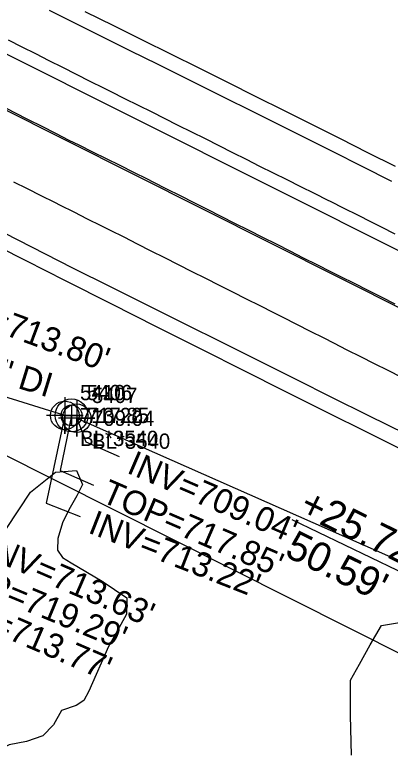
# Model space of a CAD drawing. Extents: x 1516784 to 1522736, y 634838 to 639369.
# Drawn here: x 1519791.7 to 1519853.3, y 638354.5 to 638475.3 of the extents above; entities that cross this region are included whole.
import ezdxf

# ---------------------------------------------------------------- set-up
doc = ezdxf.new("R2010")
doc.units = 0
for name, color, linetype in [('COGO Default Point Elevation', 7, 'Continuous'), ('COGO Default Point Number', 7, 'Continuous'), ('Exist Environmental Wetland Boundary Cogo Number', 7, 'Continuous'), ('Exist Environmental Wetland Boundary Text', 7, 'Continuous'), ('Exist Property Tie Line Leader', 7, 'Continuous'), ('Exist Property Tie Line Text', 7, 'Continuous'), ('Exist Right of Way Line', 7, 'Continuous'), ('Exist Utilities Sanitary Sewer Manhole CELL', 7, 'Continuous'), ('Exist Utilities Sanitary Sewer Manhole Cogo Elevation', 7, 'Continuous'), ('Exist Utilities Sanitary Sewer Manhole Cogo Number', 7, 'Continuous'), ('Exist Utilities Sanitary Sewer Manhole Leader', 7, 'Continuous'), ('Exist Utilities Sanitary Sewer Manhole Text', 7, 'Continuous'), ('Exist Utilities Sanitary Sewer UG Line', 7, 'Continuous'), ('Exist Utilities Sanitary Sewer UG Line Cogo Comment', 7, 'Continuous'), ('Exist Utilities Sanitary Sewer UG Line Cogo Elevation', 7, 'Continuous'), ('Exist Utilities Sanitary Sewer UG Line Cogo Number', 7, 'Continuous'), ('Exist Utilities Sanitary Sewer UG Line Cogo Point CELL', 7, 'Continuous'), ('Exist Utilities Sanitary Sewer UG Line Invert Elevation', 7, 'Continuous'), ('Exist Utilities Sanitary Sewer UG Line Leader', 7, 'Continuous'), ('Exist Utilities Sanitary Sewer UG Line Text', 7, 'Continuous'), ('Exist Utilities Water UG Line SUE LOS B', 7, 'Continuous'), ('Exist Vegetation Hedge Row', 7, 'Continuous')]:
    doc.layers.add(name, color=color, linetype=linetype)

msp = doc.modelspace()

# ---------------------------------------------------------------- linework, layer by layer
at = {"layer": 'COGO Default Point Elevation'}
for points in [[(1519790.67, 638471.18), (1519792.9, 638470.06), (1519795.13, 638468.93), (1519797.36, 638467.81), (1519799.59, 638466.68), (1519801.82, 638465.55), (1519804.05, 638464.43), (1519806.28, 638463.3), (1519807.48, 638462.7), (1519809.71, 638461.59), (1519811.95, 638460.48), (1519814.19, 638459.36), (1519816.25, 638458.34), (1519818.48, 638457.22), (1519820.71, 638456.11), (1519822.95, 638454.99), (1519825.18, 638453.87), (1519827.42, 638452.75), (1519829.65, 638451.63), (1519831.88, 638450.51), (1519834.12, 638449.39), (1519836.35, 638448.28), (1519838.59, 638447.16), (1519840.82, 638446.04), (1519843.06, 638444.92), (1519843.44, 638444.73), (1519845.68, 638443.61), (1519847.91, 638442.49), (1519850.15, 638441.37), (1519851.81, 638440.54), (1519854.04, 638439.42)], [(1519854.12, 638427.88), (1519851.88, 638429), (1519849.65, 638430.12), (1519847.41, 638431.24), (1519845.18, 638432.36), (1519843.56, 638433.17), (1519841.33, 638434.3), (1519839.1, 638435.42), (1519836.87, 638436.55), (1519834.64, 638437.68), (1519832.41, 638438.8), (1519830.17, 638439.93), (1519830.06, 638439.99), (1519827.83, 638441.11), (1519825.6, 638442.24), (1519823.36, 638443.36), (1519821.13, 638444.49), (1519818.9, 638445.61), (1519816.67, 638446.74), (1519814.44, 638447.87), (1519813.48, 638448.35), (1519811.24, 638449.46), (1519809, 638450.57), (1519806.76, 638451.68), (1519804.53, 638452.79), (1519802.29, 638453.91), (1519800.69, 638454.7), (1519798.46, 638455.83), (1519796.24, 638456.96), (1519794.01, 638458.09), (1519791.78, 638459.22), (1519789.56, 638460.35)], [(1519791.56, 638447.93), (1519793.8, 638446.81), (1519796.03, 638445.69), (1519798.26, 638444.57), (1519799.17, 638444.11), (1519801.41, 638442.99), (1519803.64, 638441.87), (1519805.88, 638440.75), (1519807.38, 638440), (1519809.61, 638438.88), (1519811.84, 638437.75), (1519814.07, 638436.63), (1519816.3, 638435.5), (1519818.54, 638434.38), (1519820.77, 638433.25), (1519823, 638432.13), (1519825.23, 638431), (1519827.46, 638429.88), (1519829.69, 638428.75), (1519831.92, 638427.63), (1519834.15, 638426.51), (1519835.71, 638425.72), (1519837.94, 638424.59), (1519840.17, 638423.46), (1519842.4, 638422.34), (1519843.97, 638421.54), (1519846.2, 638420.42), (1519848.43, 638419.3), (1519850.66, 638418.17), (1519852.9, 638417.05), (1519855.13, 638415.93)]]:
    msp.add_lwpolyline(points, dxfattribs=at)
at = {"layer": 'COGO Default Point Number'}
for points in [[(1519855.99, 638406.51), (1519849.67, 638409.64), (1519843.73, 638412.59), (1519837.89, 638415.51), (1519832.06, 638418.43), (1519825.95, 638421.5), (1519819.59, 638424.68), (1519813.47, 638427.73), (1519807.57, 638430.65), (1519801.28, 638433.8), (1519794.56, 638437.2), (1519787.76, 638440.67), (1519780.89, 638444.19), (1519773.8, 638447.8), (1519766.5, 638451.49), (1519759.18, 638455.17), (1519751.88, 638458.82), (1519744.56, 638462.49), (1519737.21, 638466.19), (1519729.84, 638469.9), (1519722.47, 638473.61), (1519715.13, 638477.28)], [(1519797.37, 638476.04), (1519806.15, 638471.68), (1519810.62, 638469.46), (1519815.21, 638467.18), (1519819.9, 638464.85), (1519824.69, 638462.47), (1519831.97, 638458.85), (1519836.76, 638456.45), (1519843.88, 638452.88), (1519848.65, 638450.48), (1519853.49, 638448.05)]]:
    msp.add_lwpolyline(points, dxfattribs=at)
at = {"layer": 'Exist Environmental Wetland Boundary Cogo Number'}
for points in [[(1519803.26, 638475.84), (1519807.96, 638473.51), (1519812.62, 638471.19), (1519817.28, 638468.88), (1519821.94, 638466.57), (1519826.6, 638464.25), (1519831.27, 638461.92), (1519835.91, 638459.6), (1519840.51, 638457.3), (1519845.07, 638455.01), (1519849.58, 638452.74), (1519854.09, 638450.47)], [(1519782.28, 638438.89), (1519782.81, 638439.16), (1519783.21, 638439.34), (1519783.53, 638439.46), (1519783.88, 638439.53), (1519784.05, 638439.55), (1519784.21, 638439.55), (1519784.37, 638439.54), (1519784.51, 638439.5), (1519784.82, 638439.4), (1519785.21, 638439.22), (1519786.39, 638438.64), (1519789.09, 638437.29), (1519793.55, 638435.04), (1519800, 638431.77), (1519807.48, 638427.99), (1519815.01, 638424.18), (1519822.36, 638420.49), (1519829.29, 638417.01), (1519835.92, 638413.69), (1519842.37, 638410.47), (1519850.04, 638406.65), (1519854.86, 638404.25)]]:
    msp.add_lwpolyline(points, dxfattribs=at)
at = {"layer": 'Exist Environmental Wetland Boundary Text'}
msp.add_line((1519517.96, 638596.36), (1520558.73, 638073.97), dxfattribs=at)
at = {"layer": 'Exist Property Tie Line Leader'}
msp.add_lwpolyline([(1519886.4, 638381.42), (1519858.81, 638382.15), (1519837.21, 638392.55)], dxfattribs=at)
at = {"layer": 'Exist Right of Way Line'}
msp.add_line((1519230.66, 638683.96), (1520000.91, 638297.35), dxfattribs=at)
at = {"layer": 'Exist Utilities Sanitary Sewer Manhole CELL'}
msp.add_lwpolyline([(1519801.06, 638411.36), (1519801.06, 638407.94), (1519801.06, 638409.65), (1519802.77, 638409.65), (1519799.35, 638409.65)], dxfattribs=at)
for radius in [2.69, 1.71]:
    msp.add_circle((1519801.06, 638409.65), radius, dxfattribs=at)
at = {"layer": 'Exist Utilities Sanitary Sewer Manhole Leader'}
msp.add_lwpolyline([(1519801.06, 638409.65), (1519799.17, 638400.61), (1519804.68, 638398.23)], dxfattribs=at)
at = {"layer": 'Exist Utilities Sanitary Sewer UG Line'}
for p, q in [((1519799.95, 638409.64), (1519774.57, 638417.48)), ((1519801.9, 638409.18), (1519994.43, 638324.11))]:
    msp.add_line(p, q, dxfattribs=at)
at = {"layer": 'Exist Utilities Sanitary Sewer UG Line Cogo Point CELL'}
for points in [[(1519799.95, 638412.64), (1519799.95, 638406.64), (1519799.95, 638409.64), (1519802.95, 638409.64), (1519796.95, 638409.64)], [(1519801.9, 638412.18), (1519801.9, 638406.18), (1519801.9, 638409.18), (1519804.9, 638409.18), (1519798.9, 638409.18)]]:
    msp.add_lwpolyline(points, dxfattribs=at)
for centre in [(1519799.95, 638409.64), (1519801.9, 638409.18)]:
    msp.add_circle(centre, 2.34, dxfattribs=at)
at = {"layer": 'Exist Utilities Sanitary Sewer UG Line Leader'}
for points in [[(1519799.95, 638409.64), (1519796.88, 638395.28), (1519802.47, 638393.09)], [(1519801.9, 638409.18), (1519803.38, 638405.31), (1519808.89, 638402.93)]]:
    msp.add_lwpolyline(points, dxfattribs=at)
at = {"layer": 'Exist Utilities Water UG Line SUE LOS B'}
msp.add_line((1519525.01, 638601.79), (1520075.23, 638326.13), dxfattribs=at)
at = {"layer": 'Exist Vegetation Hedge Row'}
for points in [[(1519790.42, 638391.15), (1519794.34, 638397.08), (1519798.43, 638400.35), (1519801.86, 638400.62), (1519802.86, 638398.32), (1519801.92, 638396.5), (1519800.64, 638394.2), (1519799.55, 638392.07), (1519798.82, 638389.46), (1519798.77, 638387.58), (1519799.57, 638386.39), (1519801.02, 638385.52), (1519806.08, 638382.5)], [(1519806.08, 638382.5), (1519810.1, 638379.76), (1519810.06, 638377.07), (1519808.54, 638374.31), (1519807.13, 638371.8), (1519803.91, 638364.47), (1519803.05, 638362.93), (1519801.81, 638362.11), (1519799.43, 638361.33), (1519798.12, 638358.98), (1519796.35, 638357.18), (1519793.7, 638356.23), (1519790.86, 638355.69), (1519788.31, 638354.51), (1519786.6, 638351.57)], [(1519846.92, 638353.98), (1519846.76, 638360.51), (1519846.77, 638366.27), (1519848.23, 638368.88), (1519850.02, 638372.07), (1519851.83, 638375.25), (1519855.11, 638375.79), (1519857.75, 638374.87), (1519861.51, 638372.79), (1519865.21, 638370.52), (1519864.67, 638369.39), (1519863.65, 638367.89), (1519861.72, 638366.92), (1519858.98, 638366.46), (1519856.51, 638365.58), (1519855.05, 638363.23), (1519854.67, 638361.1), (1519855.57, 638358.33), (1519856.54, 638355.61), (1519858.12, 638349.92)]]:
    msp.add_lwpolyline(points, dxfattribs=at)

# ---------------------------------------------------------------- texts
at = {"layer": 'Exist Property Tie Line Text'}
for s, p in [('+25.72', (1519838.08, 638393.6)), ("50.59'", (1519835.78, 638386.7))]:
    msp.add_text(s, height=4.8, rotation=333.828, dxfattribs=at).set_placement(p)
at = {"layer": 'Exist Utilities Sanitary Sewer Manhole Cogo Elevation'}
msp.add_text('717.85', height=2.5, dxfattribs=at).set_placement((1519803.56, 638408.4))
at = {"layer": 'Exist Utilities Sanitary Sewer Manhole Cogo Number'}
msp.add_text('5406', height=2.5, dxfattribs=at).set_placement((1519803.56, 638412.15))
at = {"layer": 'Exist Utilities Sanitary Sewer Manhole Text'}
for s, rotation, p in [("TOP=717.85'", 336.6266, (1519805.72, 638395.6)), ("TOP=719.29'", 337.4254, (1519779.96, 638383.25))]:
    msp.add_text(s, height=4, rotation=rotation, dxfattribs=at).set_placement(p)
at = {"layer": 'Exist Utilities Sanitary Sewer UG Line Cogo Comment'}
for p in [(1519802.45, 638404.64), (1519804.4, 638404.18)]:
    msp.add_text('BL*3540', height=2.5, dxfattribs=at).set_placement(p)
at = {"layer": 'Exist Utilities Sanitary Sewer UG Line Cogo Elevation'}
for s, p in [('713.22', (1519802.45, 638408.39)), ('709.04', (1519804.4, 638407.93))]:
    msp.add_text(s, height=2.5, dxfattribs=at).set_placement(p)
at = {"layer": 'Exist Utilities Sanitary Sewer UG Line Cogo Number'}
for s, p in [('5410', (1519802.45, 638412.14)), ('5407', (1519804.4, 638411.68))]:
    msp.add_text(s, height=2.5, dxfattribs=at).set_placement(p)
at = {"layer": 'Exist Utilities Sanitary Sewer UG Line Invert Elevation'}
for s, rotation, p in [("INV=713.80'", 339.5511, (1519778.77, 638427.05)), ("INV=709.04'", 336.6773, (1519809.94, 638400.31)), ("INV=713.22'", 338.5835, (1519803.6, 638390.49)), ("INV=713.63'", 336.6266, (1519786.51, 638386.63)), ("INV=713.77'", 336.6645, (1519779.49, 638377.81))]:
    msp.add_text(s, height=4, rotation=rotation, dxfattribs=at).set_placement(p)
at = {"layer": 'Exist Utilities Sanitary Sewer UG Line Text'}
msp.add_text('12" DI', height=4, rotation=342.823, dxfattribs=at).set_placement((1519783.16, 638416.92))

doc.saveas('drawing.dxf')
